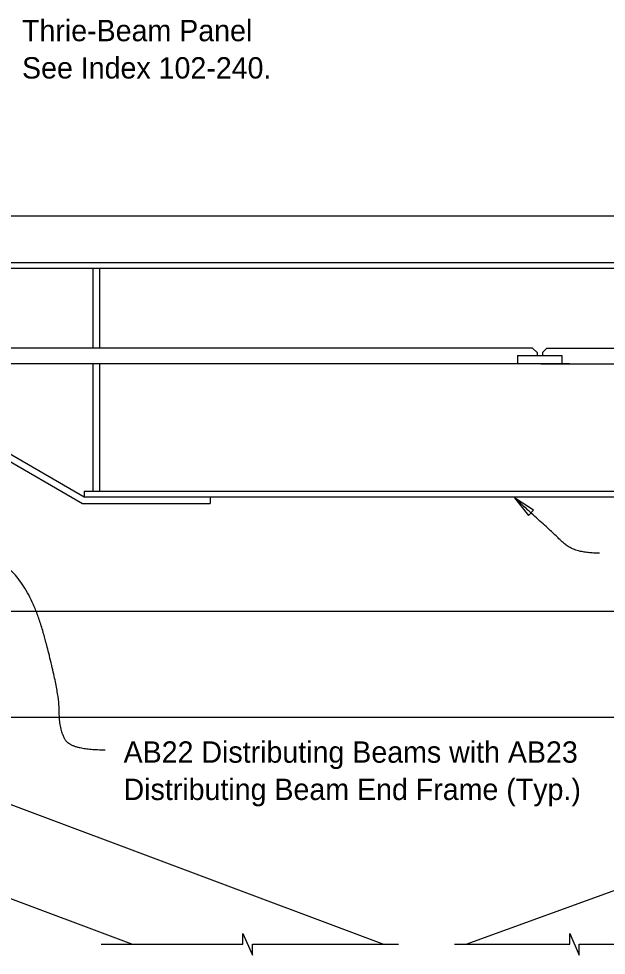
# Model space of a CAD drawing. Extents: x 11137.4 to 11208.2, y 76297.7 to 76332.4.
# Drawn here: x 11145.74 to 11151.28, y 76314.43 to 76323.26 of the extents above; entities that cross this region are included whole.
import ezdxf

# ---------------------------------------------------------------- set-up
doc = ezdxf.new("R2010")
doc.units = 0
for name, color, linetype in [('Dimension', 7, 'Continuous'), ('Miscellaneous', 7, 'Continuous'), ('SteelMisc', 7, 'Continuous'), ('Symbols', 7, 'Continuous'), ('TextStructures', 7, 'Continuous'), ('Wood', 7, 'Continuous')]:
    doc.layers.add(name, color=color, linetype=linetype)

msp = doc.modelspace()

# ---------------------------------------------------------------- linework, layer by layer
at = {"layer": 'Dimension'}
msp.add_lwpolyline([(11150.4167, 76318.7419), (11150.5474, 76318.576), (11150.5948, 76318.6283)], close=True, dxfattribs=at)
for points in [[(11151.2173, 76318.221), (11150.9762, 76318.221), (11150.7736, 76318.4188), (11150.4167, 76318.7419)], [(11146.5537, 76316.3631), (11146.2354, 76316.3631), (11146.1197, 76316.556), (11146.1197, 76316.9225), (11145.8303, 76317.9811), (11145.2709, 76318.3042), (11144.4606, 76318.555)]]:
    msp.add_open_spline(points, degree=2, dxfattribs=at)
at = {"layer": 'Miscellaneous'}
msp.add_line((11168.9456, 76321.3996), (11144.9456, 76321.3996), dxfattribs=at)
at = {"layer": 'SteelMisc'}
for p, q in [((11144.3439, 76320.9621), (11169.5474, 76320.9621)), ((11144.3439, 76320.91), (11169.5474, 76320.91)), ((11146.4396, 76320.1562), (11146.4396, 76320.91)), ((11146.5021, 76320.1562), (11146.5021, 76320.91)), ((11150.5867, 76320.1562), (11144.7211, 76320.1562)), ((11150.5867, 76320.1562), (11150.6284, 76320.1143)), ((11150.721, 76320.1562), (11150.6793, 76320.1143)), ((11150.721, 76320.1562), (11156.8785, 76320.1562)), ((11150.4441, 76320.0871), (11150.8635, 76320.0871)), ((11150.4441, 76320.0871), (11150.4441, 76320.0062)), ((11150.6284, 76320.1143), (11150.6284, 76320.0871)), ((11150.6793, 76320.1143), (11150.6793, 76320.0871)), ((11150.8635, 76320.0871), (11150.8635, 76320.0062)), ((11150.936, 76320.0062), (11144.5178, 76320.0062)), ((11146.4396, 76318.8059), (11146.4396, 76320.0062)), ((11146.5021, 76318.8059), (11146.5021, 76320.0062)), ((11150.6637, 76320.0062), (11157.1186, 76320.0062)), ((11144.4272, 76319.7954), (11146.3396, 76318.6913)), ((11144.444, 76319.8579), (11146.3563, 76318.7538)), ((11146.3563, 76318.8059), (11167.535, 76318.8059)), ((11146.3563, 76318.8059), (11146.3563, 76318.7538)), ((11146.3563, 76318.7538), (11167.535, 76318.7538)), ((11147.5427, 76318.7538), (11147.5427, 76318.6913)), ((11146.3396, 76318.6913), (11147.5427, 76318.6913)), ((11141.7822, 76317.6731), (11172.1351, 76317.6731))]:
    msp.add_line(p, q, dxfattribs=at)
at = {"layer": 'Symbols'}
for points in [[(11146.5159, 76314.5307), (11147.8526, 76314.5307), (11147.8526, 76314.634), (11147.9426, 76314.4274), (11147.9426, 76314.5307), (11149.32, 76314.5307)], [(11149.8483, 76314.5307), (11150.9368, 76314.5307), (11150.9368, 76314.634), (11151.0268, 76314.4274), (11151.0268, 76314.5307), (11152.648, 76314.5307)]]:
    msp.add_lwpolyline(points, dxfattribs=at)
at = {"layer": 'Wood'}
for p, q in [((11139.4456, 76317.6731), (11156.9456, 76317.6731)), ((11140.9378, 76317.621), (11149.1786, 76314.5307)), ((11146.8054, 76314.5307), (11140.2943, 76316.9724)), ((11143.4656, 76316.6731), (11155.6013, 76316.6731)), ((11149.9598, 76314.5307), (11155.7264, 76316.6276))]:
    msp.add_line(p, q, dxfattribs=at)

# ---------------------------------------------------------------- texts
at = {"layer": 'Dimension'}
for s, p in [('AB22 Distributing Beams with AB23 ', (11146.7273, 76316.2441)), ('Distributing Beam End Frame (Typ.)', (11146.7273, 76315.8921))]:
    msp.add_text(s, height=0.2016, dxfattribs=at).set_placement(p)
at = {"layer": 'TextStructures'}
for s, p in [('Thrie-Beam Panel', (11145.769, 76323.0512)), ('See Index 102-240.', (11145.769, 76322.6992))]:
    msp.add_text(s, height=0.2016, dxfattribs=at).set_placement(p)

doc.saveas('drawing.dxf')
